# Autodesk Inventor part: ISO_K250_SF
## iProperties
Created: 2005-11
Part Number: ISO_K250_SF
Material: 1.4301 X5CrNi10-10 A2
Description: Schweißlansch DN250 ISO-K
Document SubType Name: Modellieren
Designer: Mittelmeyer
Manufacturer: Standard
Standards Organization: Custom
Author: Mittelmeyer
Comments: LEYBOLD
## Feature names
1. Extrusion2
2. Extrusion3
3. Extrusion4
4. Drehung1 [Revolution]
5. Bohrung1 [Hole]
6. Extrusion5
